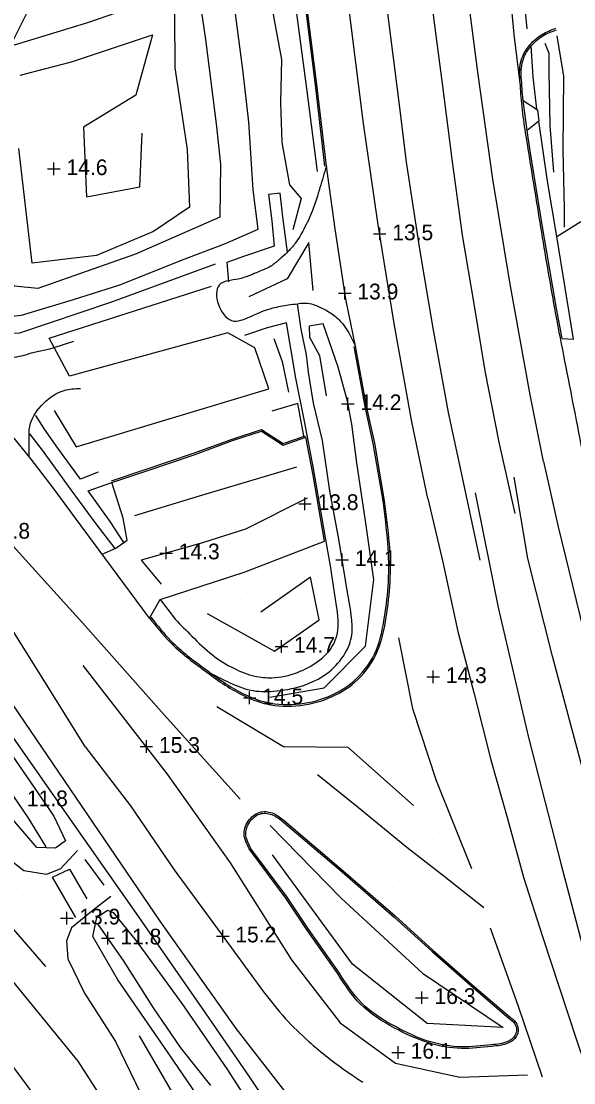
# Model space of a CAD drawing. Extents: x 2316231 to 2323598, y 363169 to 371906.
# Drawn here: x 2317829 to 2318004.5, y 368745.7 to 369083.2 of the extents above; entities that cross this region are included whole.
import ezdxf

# ---------------------------------------------------------------- set-up
doc = ezdxf.new("R2010")
doc.units = 0
for name, color, linetype in [('RD_DTM_BkLn1', 7, 'Continuous'), ('RD_DTM_Spot', 7, 'Continuous'), ('RD_DTM_Void', 7, 'Continuous'), ('RD_EX_H2O', 7, 'Continuous'), ('RD_EX_Road', 7, 'Continuous')]:
    doc.layers.add(name, color=color, linetype=linetype)

msp = doc.modelspace()

# ---------------------------------------------------------------- linework, layer by layer
at = {"layer": 'RD_DTM_BkLn1'}
msp.add_line((2317849.169, 368816.632), (2317855.169, 368808.532), dxfattribs=at)
for points in [[(2317782.837, 369460.705), (2317782.594, 369432.642), (2317782.438, 369391.736), (2317782.714, 369355.792), (2317786.981, 369336.313), (2317794.399, 369307.852), (2317804.873, 369274.863), (2317815.931, 369232.668), (2317820.146, 369203.448), (2317820.711, 369190.542), (2317821.19, 369170.485), (2317822.084, 369161.146), (2317826.2, 369140.318), (2317830.794, 369114.952), (2317834.404, 369093.232), (2317825.488, 369075.338), (2317850.452, 369082.918), (2317873.473, 369090.997)], [(2317908.843, 369381.485), (2317913.513, 369354.817), (2317918.561, 369325.008), (2317923.344, 369290.295), (2317926.084, 369262.145), (2317927.968, 369248.062), (2317930.672, 369222.156), (2317933.034, 369196.802), (2317936.478, 369166.238), (2317938.559, 369144.418), (2317941.81, 369115.562), (2317945.02, 369088.269), (2317948.964, 369057.487), (2317951.287, 369038.4), (2317955.603, 369010.158), (2317959.783, 368985.654), (2317964.643, 368958.806), (2317969.083, 368938.18), (2317974.686, 368911.913)], [(2317916.239, 369382.855), (2317920.659, 369363.076), (2317925.031, 369338.69), (2317929.222, 369313.911), (2317933.826, 369288.294), (2317937.194, 369266.05), (2317940.518, 369239.783), (2317943.884, 369214.853), (2317947.129, 369189.53), (2317949.991, 369164.089), (2317954.201, 369131.623), (2317956.494, 369111.461), (2317959.647, 369086.771), (2317962.687, 369063.395), (2317965.831, 369039.362), (2317969.07, 369015.196), (2317972.715, 368993.345), (2317976.292, 368972.078), (2317980.697, 368949.435), (2317985.805, 368926.656)], [(2317958.165, 368931.47), (2317953.061, 368955.847), (2317947.508, 368987.139), (2317942.385, 369018.464), (2317937.684, 369050.73), (2317932.966, 369088.69), (2317928.63, 369124.464), (2317925.05, 369158.539), (2317921.243, 369197.354), (2317918.129, 369233.825), (2317914.604, 369267.159), (2317911.032, 369296.209)], [(2317994.945, 368943.256), (2317990.683, 368964.434), (2317984.279, 368999.646), (2317978.809, 369032.991), (2317974.046, 369067), (2317969.529, 369102.297), (2317965.699, 369136.612), (2317961.803, 369172.109), (2317957.617, 369209.135), (2317954.279, 369234.829)], [(2317875.025, 369159.136), (2317877.216, 369130.751), (2317884.286, 369099.773), (2317887.499, 369077.387), (2317890.939, 369050.654), (2317892.28, 369037.767), (2317892.072, 369020.973), (2317865.295, 369009.189), (2317834.297, 368998.227), (2317826.722, 368999.043), (2317822.263, 369015.909), (2317815.09, 369061.486), (2317804.133, 369095.731), (2317789.806, 369131.557), (2317777.472, 369153.49), (2317763.205, 369178.024), (2317749.221, 369201.912)], [(2317901.802, 369182.26), (2317888.046, 369179.11), (2317875.054, 369175.824), (2317864.943, 369173.514), (2317858.341, 369168.786), (2317859.068, 369150.554), (2317862.756, 369127.747), (2317868.673, 369106.504), (2317876.636, 369097.701), (2317877.632, 369085.21), (2317877.723, 369068.45), (2317881.693, 369042.431), (2317882.467, 369024.103), (2317871.039, 369016.381), (2317852.939, 369008.765), (2317832.43, 369006.342), (2317828.265, 369042.76)], [(2317923.124, 369035.444), (2317919.706, 369061.855), (2317915.311, 369095.337), (2317913.324, 369114.733), (2317910.313, 369136.963)], [(2317989.708, 369080.824), (2317987.704, 369101.437), (2317986.394, 369117.929)], [(2317907.819, 369091.712), (2317911.673, 369071.052), (2317911.363, 369057.434), (2317911.797, 369044.719), (2317914.233, 369031.17), (2317917.875, 369026.889), (2317915.292, 369016.912)], [(2317819.387, 368988.852), (2317829.096, 368989.803), (2317845.595, 368994.742), (2317860.266, 368999.368), (2317880.721, 369007.544), (2317893.866, 369012.596), (2317904.299, 369017.173), (2317902.61, 369029.655), (2317901.243, 369051.125), (2317899.477, 369067.046), (2317896.552, 369089.598)], [(2317890.632, 369005.976), (2317857.36, 368993.809), (2317828.445, 368984.017), (2317815.219, 368983.956), (2317806.887, 368988.559), (2317787.699, 369012.486), (2317769.023, 369036.112), (2317751.729, 369054.741), (2317732.933, 369078.272), (2317732.896, 369078.01)], [(2317828.591, 369066.059), (2317844.99, 369070.317), (2317870.652, 369078.944), (2317865.335, 369059.765), (2317848.737, 369049.599), (2317849.682, 369027.415), (2317866.614, 369030.621), (2317867.432, 369047.674)], [(2317998.158, 369035.204), (2317996.995, 369050.132), (2317996.703, 369067.191), (2317996.698, 369072.956), (2317995.377, 369076.127)], [(2317921.696, 368997.624), (2317920.308, 369012.91), (2317913.455, 369001.284), (2317901.309, 368995.618)], [(2317839.455, 368979.505), (2317837.891, 368982.452), (2317889.414, 368998.976)], [(2317907.939, 368868.265), (2317925.179, 368871.236), (2317938.338, 368884.554), (2317940.948, 368905.693), (2317938.401, 368924.34), (2317935.625, 368942.868), (2317934.003, 368955.099), (2317932.6, 368962.412), (2317929.649, 368973.231), (2317924.935, 368987.019), (2317920.466, 368986.29), (2317920.567, 368982.816), (2317923.688, 368976.939), (2317925.829, 368964.119)], [(2317839.489, 368959.477), (2317846.471, 368947.897), (2317907.613, 368966.34), (2317903.241, 368979.398), (2317894.636, 368984.182), (2317844.321, 368970.338), (2317839.455, 368979.505)], [(2317909.237, 368982.339), (2317911.884, 368975.043), (2317913.898, 368965.292)], [(2317994.945, 368943.256), (2317999.581, 368922.486), (2318006.415, 368894.237), (2318012.687, 368867.615), (2318018.739, 368844.567), (2318025.715, 368820.723), (2318032.954, 368796.181), (2318042.568, 368767.866), (2318051.932, 368740.972), (2318061.741, 368713.692), (2318072.652, 368684.171), (2318080.313, 368665.019), (2318090.671, 368641.168), (2318103.423, 368611.607), (2318115.122, 368584.84), (2318126.37, 368560.77), (2318140.521, 368532.325), (2318153.45, 368506.603), (2318162.871, 368489.204)], [(2317865.089, 368926.113), (2317885.61, 368932.278), (2317916.511, 368941.55)], [(2318049.725, 368711.287), (2318038.436, 368743.806), (2318025.343, 368782.851), (2318010.603, 368833.332), (2317997.722, 368881.343), (2317989.895, 368912.373), (2317985.583, 368938.233)], [(2317973.165, 368933.326), (2317980.474, 368896.809), (2317990.144, 368855.473), (2318000.477, 368814.942), (2318011.363, 368773.94), (2318020.296, 368747.721), (2318037.2, 368706.91)], [(2317919.775, 368931.542), (2317900.233, 368921.728), (2317886.6, 368917.389), (2317867.092, 368911.908), (2317873.394, 368904.192)], [(2317958.165, 368931.47), (2317962.911, 368911.229), (2317967.737, 368889.219), (2317972.844, 368869.387), (2317978.118, 368848.411), (2317983.54, 368829.336), (2317988.579, 368811.044), (2317994.567, 368792.221)], [(2317782.634, 368912.285), (2317800.725, 368886.275), (2317823.579, 368853.442), (2317839.367, 368830.446), (2317843.056, 368822.615), (2317839.886, 368820.239), (2317833.965, 368820.493), (2317822.49, 368833.864), (2317804.686, 368859.429), (2317784.487, 368890.065), (2317765.162, 368918.906)], [(2317823.435, 368919.645), (2317849.355, 368890.862), (2317874.362, 368862.634), (2317898.577, 368835.84)], [(2317849.404, 368852.423), (2317836.116, 368873.741), (2317814.133, 368908.81)], [(2317739.872, 368905.687), (2317755.854, 368883.436), (2317774.209, 368851.564), (2317791.535, 368822.186), (2317810.014, 368797.21), (2317825.222, 368779.112), (2317847.007, 368752.516), (2317865.549, 368723.472)], [(2317888.08, 368894.881), (2317909.487, 368882.896), (2317923.602, 368892.914), (2317920.924, 368906.435), (2317905.134, 368895.349)], [(2317800.727, 368903.713), (2317822.559, 368871.316), (2317848.195, 368833.555), (2317873.003, 368797.108), (2317897.118, 368762.937), (2317918.852, 368734.909), (2317938.14, 368706.056), (2317957.247, 368676.396), (2317975.021, 368648.353), (2317993.334, 368624.472), (2318012.682, 368595.462), (2318033.529, 368563.765), (2318053.633, 368533.466), (2318080.086, 368495.162), (2318097.769, 368469.694), (2318114.655, 368442.844), (2318134.076, 368413.87), (2318156.078, 368381.786), (2318175.29, 368356.772), (2318189.565, 368335.319)], [(2317948.79, 368887.178), (2317953.254, 368864.676), (2317960.834, 368841.793), (2317972.061, 368813.788)], [(2317848.558, 368878.372), (2317875.392, 368843.822), (2317895.368, 368815.593), (2317914.809, 368784.777), (2317930.265, 368764.706), (2317947.844, 368751.959), (2317968.354, 368747.473), (2317989.861, 368748.22)], [(2317737.77, 368869.106), (2317762.435, 368833.069), (2317782.409, 368804.274), (2317803.724, 368777.39), (2317826.495, 368750.527), (2317851.718, 368716.51), (2317871.057, 368688.656), (2317887.695, 368664.141), (2317900.422, 368644.641), (2317922.352, 368623.953), (2317937.967, 368610.404), (2317954.549, 368593.098), (2317970.651, 368565.106), (2317989.68, 368538.637), (2318005.909, 368519.466), (2318020.25, 368501.262), (2318038.781, 368477.73), (2318045.117, 368463.888), (2318053.174, 368450.368), (2318065.283, 368434.72)], [(2317891.096, 368865.377), (2317912.273, 368852.659), (2317932.744, 368852.445), (2317953.571, 368833.89)], [(2317849.404, 368852.423), (2317863.66, 368833.726), (2317877.588, 368813.369), (2317893.654, 368791.419), (2317905.929, 368774.579)], [(2317923.109, 368843.681), (2317936.168, 368833.206), (2317951.472, 368820.549), (2317962.766, 368811.775), (2317975.921, 368801.42)], [(2317836.759, 368782.613), (2317825.859, 368795.225), (2317809.518, 368818.356), (2317795.654, 368840.217)], [(2317908.078, 368827.527), (2317930.605, 368804.383), (2317956.5, 368780.522), (2317982.096, 368763.208), (2317957.933, 368764.489), (2317934.254, 368783.387), (2317908.756, 368818.175)], [(2317846.361, 368798.225), (2317838.867, 368811.023), (2317844.324, 368813.598), (2317849.804, 368804.163)], [(2317859.676, 368778.459), (2317851.703, 368792.148), (2317852.992, 368798.199), (2317856.415, 368800.514), (2317858.206, 368799.8), (2317865.48, 368790.818), (2317880.01, 368770.893), (2317894.322, 368750.114), (2317906.16, 368731.699)], [(2317977.989, 368794.917), (2317986.745, 368770.323), (2317994.481, 368747.596)], [(2317994.567, 368792.221), (2318005.231, 368759.632), (2318018.958, 368719.225)], [(2317889.139, 368735.491), (2317874.444, 368756.945), (2317859.676, 368778.459)], [(2317892.798, 368719.321), (2317877.144, 368742.329), (2317866.521, 368760.609)]]:
    msp.add_lwpolyline(points, dxfattribs=at)
msp.add_spline([(2317905.929, 368774.579), (2317912.878, 368766.152), (2317920.336, 368758.794), (2317933.143, 368748.778), (2317937.469, 368745.868)], degree=3, dxfattribs=at)
at = {"layer": 'RD_DTM_Spot'}
for p, q in [((2317841.798, 369060.176), (2317841.798, 369060.176)), ((2317839.368, 369036.315), (2317839.368, 369036.315)), ((2317873.96, 369029.388), (2317873.96, 369029.388)), ((2317840.747, 369019.274), (2317840.747, 369019.274)), ((2318004.217, 369009.27), (2318004.217, 369009.27)), ((2317916.334, 368997.246), (2317916.334, 368997.246)), ((2317844.335, 368914.067), (2317844.335, 368914.067)), ((2317900.767, 368901.702), (2317900.767, 368901.702)), ((2317955.252, 368897.863), (2317955.252, 368897.863)), ((2317836.973, 368889.624), (2317836.973, 368889.624)), ((2317938.642, 368864.094), (2317938.642, 368864.094)), ((2317907.04, 368842.272), (2317907.04, 368842.272)), ((2317972.823, 368831.839), (2317972.823, 368831.839)), ((2317925.183, 368829.151), (2317925.183, 368829.151)), ((2317959.685, 368822.998), (2317959.685, 368822.998)), ((2317949.126, 368809.951), (2317949.126, 368809.951)), ((2317829.732, 368805.073), (2317829.732, 368805.073)), ((2317982.808, 368802.97), (2317982.808, 368802.97)), ((2317969.594, 368791.698), (2317969.594, 368791.698)), ((2317992.473, 368776.039), (2317992.473, 368776.039)), ((2317843.861, 368766.664), (2317843.861, 368766.664))]:
    msp.add_line(p, q, dxfattribs=at)
at = {"layer": 'RD_DTM_Void'}
for p, q in [((2317839.368, 369034.315), (2317839.368, 369038.315)), ((2317837.368, 369036.315), (2317841.368, 369036.315)), ((2317942.853, 369013.603), (2317942.853, 369017.603)), ((2317940.853, 369015.603), (2317944.853, 369015.603)), ((2317929.769, 368996.796), (2317933.769, 368996.796)), ((2317931.769, 368994.796), (2317931.769, 368998.796)), ((2317932.761, 368959.571), (2317932.761, 368963.571)), ((2317930.761, 368961.571), (2317934.761, 368961.571)), ((2317917.121, 368929.81), (2317921.121, 368929.81)), ((2317919.121, 368927.81), (2317919.121, 368931.81)), ((2317875.021, 368912.136), (2317875.021, 368916.136)), ((2317873.021, 368914.136), (2317877.021, 368914.136)), ((2317928.961, 368911.982), (2317932.961, 368911.982)), ((2317930.961, 368909.982), (2317930.961, 368913.982)), ((2317911.633, 368882.418), (2317911.633, 368886.418)), ((2317909.633, 368884.418), (2317913.633, 368884.418)), ((2317957.883, 368874.783), (2317961.883, 368874.783)), ((2317959.883, 368872.783), (2317959.883, 368876.783)), ((2317899.548, 368868.05), (2317903.548, 368868.05)), ((2317901.548, 368866.05), (2317901.548, 368870.05)), ((2317868.733, 368850.583), (2317868.733, 368854.583)), ((2317866.733, 368852.583), (2317870.733, 368852.583)), ((2317841.424, 368798.015), (2317845.424, 368798.015)), ((2317843.424, 368796.015), (2317843.424, 368800.015)), ((2317856.48, 368789.656), (2317856.48, 368793.656)), ((2317892.993, 368790.323), (2317892.993, 368794.323)), ((2317854.48, 368791.656), (2317858.48, 368791.656)), ((2317890.993, 368792.323), (2317894.993, 368792.323)), ((2317956.278, 368770.736), (2317956.278, 368774.736)), ((2317954.278, 368772.736), (2317958.278, 368772.736)), ((2317948.706, 368753.339), (2317948.706, 368757.339)), ((2317946.706, 368755.339), (2317950.706, 368755.339))]:
    msp.add_line(p, q, dxfattribs=at)
at = {"layer": 'RD_EX_H2O'}
for points in [[(2317836.951, 368820.715), (2317831.194, 368830.054), (2317826.576, 368836.744), (2317820.807, 368845.83), (2317810.608, 368859.861), (2317799.347, 368877.926), (2317788.062, 368896.051), (2317779.619, 368909.656)], [(2317889.172, 368744.77), (2317879.715, 368756.825), (2317871.005, 368769.529), (2317861.47, 368784.581), (2317853.54, 368795.887)]]:
    msp.add_lwpolyline(points, dxfattribs=at)
at = {"layer": 'RD_EX_Road'}
for p, q in [((2317989.749, 369048.547), (2317988.459, 369058.061)), ((2317839.455, 368979.505), (2317845.704, 368981.467)), ((2317835.734, 368946.865), (2317831.699, 368952.087)), ((2317873.082, 368899.379), (2317877.942, 368892.966))]:
    msp.add_line(p, q, dxfattribs=at)
for points in [[(2317987.555, 369062.728), (2317985.545, 369079.019), (2317983.899, 369097.494), (2317980.724, 369127.055), (2317976.272, 369165.67), (2317970.907, 369205.341), (2317964.121, 369256.359), (2317958.486, 369292.652), (2317955.508, 369314.214), (2317954.744, 369318.623), (2317953.823, 369325.109), (2317952.473, 369334.069), (2317948.805, 369353.832), (2317945.69, 369369.736), (2317941.235, 369387.474), (2317936.745, 369407.432), (2317932.055, 369425.911), (2317926.95, 369447.078), (2317921.049, 369468.918), (2317915.283, 369489.122)], [(2317925.927, 369037.172), (2317922.936, 369063.103), (2317920.162, 369084.866), (2317917.51, 369107.274), (2317914.944, 369130.063), (2317912.703, 369148.672)], [(2317925.43, 369037.115), (2317922.439, 369063.043), (2317919.665, 369084.805), (2317917.013, 369107.217), (2317914.448, 369130.005), (2317914.039, 369133.401)], [(2317839.078, 368934.859), (2317832.09, 368944.01), (2317817.502, 368961.92), (2317801.462, 368980.638), (2317779.258, 369005.225), (2317758.916, 369029.91), (2317740.509, 369052.461), (2317719.943, 369077.779)], [(2317999.103, 369078.578), (2318001.291, 369065.746), (2318001, 369042.256), (2318001.476, 369023.728), (2318001.492, 369017.807)], [(2317992.733, 369055.312), (2317991.657, 369065.546), (2317991.02, 369075.404)], [(2318000.873, 368982.331), (2318004.456, 368982.184), (2317999.185, 369014.799), (2318017.772, 369026.435), (2318036.54, 369038.428), (2318051.015, 369046.624), (2318068.605, 369056.977), (2318084.621, 369065.523), (2318095.368, 369071.85)], [(2317988.459, 369058.061), (2317993.035, 369055.118), (2317993.445, 369051.416)], [(2317993.445, 369051.416), (2317993.445, 369051.416), (2317989.749, 369048.547)], [(2317999.185, 369014.799), (2317996.15, 369032.422), (2317993.445, 369051.416)], [(2318000.873, 368982.331), (2317999.019, 368991.938), (2317994.573, 369017.845), (2317990.551, 369042.638), (2317989.749, 369048.547)], [(2317935.199, 368979.934), (2317932.066, 368994.836), (2317928.674, 369017.187), (2317925.927, 369037.172)], [(2317913.554, 369009.853), (2317912.114, 369021.035), (2317911.211, 369028.607), (2317907.496, 369028.114), (2317908.622, 369019.74), (2317909.379, 369011.703), (2317899.873, 369008.542), (2317894.335, 369006.47), (2317894.793, 369000.404)], [(2317919.61, 368977.166), (2317917.955, 368985.373), (2317916.716, 368993.401)], [(2317914.739, 368978.584), (2317913.202, 368987.295), (2317907.142, 368985.704), (2317899.931, 368983.343)], [(2317833.057, 368978.013), (2317838.076, 368979.073), (2317839.455, 368979.505)], [(2317943.925, 368930.708), (2317940.817, 368948.946), (2317938.225, 368960.753), (2317934.707, 368979.843)], [(2317944.42, 368930.778), (2317941.307, 368949.041), (2317938.715, 368960.852), (2317935.199, 368979.934)], [(2317929.135, 368897.343), (2317927.201, 368910.019), (2317925.693, 368919.001), (2317921.781, 368941.057), (2317918.926, 368956.058), (2317916.188, 368969.748), (2317914.739, 368978.584)], [(2317932.79, 368900.933), (2317929.868, 368918.582), (2317927.025, 368933.873), (2317924.641, 368949.884), (2317921.875, 368961.744), (2317920.248, 368971.688), (2317919.61, 368977.166)], [(2317918.717, 368951.232), (2317918.674, 368951.946), (2317916.839, 368961.672), (2317908.578, 368959.28)], [(2317840.586, 368947.516), (2317836.366, 368953.525), (2317833.645, 368957.904)], [(2317857.65, 368937.086), (2317868.704, 368940.756), (2317883.739, 368945.859), (2317895.942, 368950.346), (2317905.332, 368953.425), (2317912.224, 368948.936), (2317919.266, 368951.426)], [(2317857.807, 368936.611), (2317868.863, 368940.282), (2317883.906, 368945.388), (2317896.107, 368949.874), (2317905.26, 368952.875), (2317912.158, 368948.383), (2317919.432, 368950.954)], [(2317869.724, 368893.465), (2317873.082, 368899.379), (2317899.83, 368908.045), (2317925.305, 368917.894), (2317921.753, 368938.866), (2317919.432, 368950.954)], [(2317858.809, 368915.579), (2317852.832, 368923.432), (2317844.841, 368934.209), (2317835.734, 368946.865)], [(2317853.398, 368939.858), (2317847.833, 368937.608), (2317840.586, 368947.516)], [(2317861.603, 368917.46), (2317857.263, 368924.145), (2317850.28, 368933.932), (2317857.807, 368936.611)], [(2317854.674, 368913.798), (2317858.989, 368915.656), (2317862.641, 368918.176), (2317861.393, 368925.183), (2317857.807, 368936.611)], [(2317869.724, 368893.465), (2317861.24, 368904.917), (2317846.205, 368925.252), (2317839.078, 368934.859)], [(2317846.901, 368819.562), (2317841.412, 368813.725), (2317837.015, 368811.869), (2317829.809, 368813.052), (2317818.492, 368821.862), (2317803.608, 368839.694), (2317790.398, 368858.1), (2317777.38, 368881.62), (2317764.443, 368904.129), (2317749.812, 368927.593)], [(2317786.898, 368914.25), (2317805.913, 368886.757), (2317824, 368858.821), (2317845.619, 368827.905), (2317865.487, 368799.531), (2317886.421, 368769.303), (2317901.489, 368747.439), (2317917.083, 368724.238)], [(2317912.305, 368828.586), (2317930.96, 368812.716), (2317947.482, 368798.34)], [(2317912.607, 368828.986), (2317931.286, 368813.095), (2317947.814, 368798.714)], [(2317929.637, 368780.22), (2317919.836, 368794.226), (2317913.022, 368804.398), (2317901.407, 368820.08)], [(2317930.043, 368780.513), (2317920.248, 368794.508), (2317913.431, 368804.686), (2317901.856, 368820.315)], [(2317857.471, 368804.916), (2317851.793, 368800.572), (2317844.933, 368794.991), (2317843.408, 368790.818), (2317843.829, 368785.089), (2317849.112, 368774.186), (2317858.875, 368758.784), (2317868.603, 368738.906)], [(2317947.482, 368798.34), (2317959.432, 368787.483), (2317972.578, 368775.921), (2317983.962, 368766.139)], [(2317947.814, 368798.714), (2317959.765, 368787.856), (2317972.906, 368776.298), (2317984.293, 368766.513)]]:
    msp.add_lwpolyline(points, dxfattribs=at)
for points in [[(2317987.555, 369062.728), (2317987.304, 369066.321), (2317988.302, 369072.177), (2317990.709, 369075.841), (2317994.438, 369079.044), (2317998.841, 369081.014)], [(2317988.054, 369062.763), (2317987.807, 369066.296), (2317988.777, 369071.99), (2317991.088, 369075.508), (2317994.708, 369078.618), (2317999.045, 369080.558)], [(2318007.264, 368946.586), (2318004.267, 368962.107), (2317998.527, 368991.848), (2317994.079, 369017.762), (2317990.056, 369042.564), (2317987.804, 369059.168), (2317987.555, 369062.728)], [(2317988.459, 369058.061), (2317988.301, 369059.22), (2317988.054, 369062.763)], [(2317925.927, 369037.172), (2317923.886, 369030.379), (2317921.531, 369023.062), (2317918.719, 369017.085), (2317916.057, 369012.694), (2317913.355, 369009.629), (2317911.005, 369007.516), (2317908.308, 369005.37), (2317905.914, 369004.213), (2317901.296, 369002.291), (2317897.949, 369001.27), (2317891.911, 368999.344), (2317895.802, 368988.056), (2317901.885, 368989.384), (2317908.954, 368992.069), (2317913.829, 368993.034), (2317916.716, 368993.401)], [(2317916.716, 368993.401), (2317918.607, 368993.641), (2317923.602, 368992.457), (2317927.161, 368990.552), (2317930.347, 368987.898), (2317935.199, 368979.934)], [(2317799.747, 368982.537), (2317804.015, 368980.41), (2317812.57, 368977.369), (2317820.132, 368976.147), (2317826.782, 368976.375), (2317833.057, 368978.013)], [(2317831.483, 368944.756), (2317831.515, 368948.119), (2317831.838, 368955.088), (2317836.099, 368961.727), (2317842.566, 368965.835), (2317847.858, 368966.487)], [(2317869.724, 368893.465), (2317876.182, 368885.893), (2317887.222, 368876.747), (2317899.143, 368869.018), (2317906.863, 368866.161), (2317917.573, 368865.681), (2317927.748, 368868.474), (2317935.872, 368873.872), (2317942.198, 368882.981), (2317944.905, 368893.758), (2317946.145, 368904.887), (2317945.943, 368917.199), (2317944.42, 368930.778)], [(2317870.104, 368893.789), (2317876.534, 368886.25), (2317887.518, 368877.15), (2317899.369, 368869.468), (2317906.964, 368866.657), (2317917.517, 368866.184), (2317927.539, 368868.935), (2317935.515, 368874.236), (2317941.735, 368883.191), (2317944.412, 368893.847), (2317945.644, 368904.911), (2317945.444, 368917.167), (2317943.925, 368930.708)], [(2317890.106, 368875.473), (2317895.962, 368872.539), (2317902.624, 368870.383), (2317910.073, 368870.294), (2317919.501, 368872.332), (2317926.767, 368876.395), (2317931.834, 368882.185), (2317934.001, 368888.162), (2317933.905, 368893.565), (2317932.79, 368900.933)], [(2317877.942, 368892.966), (2317883.19, 368887.719), (2317889.712, 368881.724), (2317896.55, 368877.472), (2317903.188, 368874.979), (2317908.566, 368874.498), (2317916.778, 368876.177), (2317923.308, 368879.713), (2317926.781, 368882.954), (2317929.441, 368888.677), (2317929.135, 368897.343)], [(2317901.407, 368820.08), (2317899.793, 368824.862), (2317901.5, 368829.419), (2317905.115, 368831.794), (2317909.182, 368831.28), (2317912.607, 368828.986)], [(2317901.856, 368820.315), (2317900.323, 368824.853), (2317901.911, 368829.091), (2317905.236, 368831.275), (2317909.002, 368830.798), (2317912.305, 368828.586)], [(2317984.293, 368766.513), (2317986.119, 368764.848), (2317986.86, 368762.669), (2317986.253, 368760.335), (2317983.83, 368758.343), (2317978.4, 368757.247), (2317968.831, 368756.582), (2317958.485, 368758.326), (2317947.592, 368763.091), (2317936.741, 368770.709), (2317929.637, 368780.22)], [(2317983.962, 368766.139), (2317985.687, 368764.566), (2317986.339, 368762.649), (2317985.81, 368760.618), (2317983.609, 368758.808), (2317978.333, 368757.744), (2317968.855, 368757.085), (2317958.629, 368758.809), (2317947.838, 368763.529), (2317937.094, 368771.072), (2317930.043, 368780.513)]]:
    msp.add_spline(points, degree=3, dxfattribs=at)

# ---------------------------------------------------------------- texts
at = {"layer": 'RD_DTM_Void'}
for s, p in [('14.6', (2317843.368, 369034.315)), ('13.5', (2317946.853, 369013.603)), ('13.9', (2317935.769, 368994.796)), ('14.2', (2317936.761, 368959.571)), ('13.8', (2317923.121, 368927.81)), ('14.8', (2317818.767, 368918.705)), ('14.3', (2317879.021, 368912.136)), ('14.1', (2317934.961, 368909.982)), ('14.7', (2317915.633, 368882.418)), ('14.3', (2317963.883, 368872.783)), ('14.5', (2317905.548, 368866.05)), ('15.3', (2317872.733, 368850.583)), ('11.8', (2317830.766, 368833.612)), ('13.9', (2317847.424, 368796.015)), ('11.8', (2317860.48, 368789.656)), ('15.2', (2317896.993, 368790.323)), ('16.3', (2317960.278, 368770.736)), ('16.1', (2317952.706, 368753.339))]:
    msp.add_text(s, height=5, dxfattribs=at).set_placement(p)

doc.saveas('drawing.dxf')
